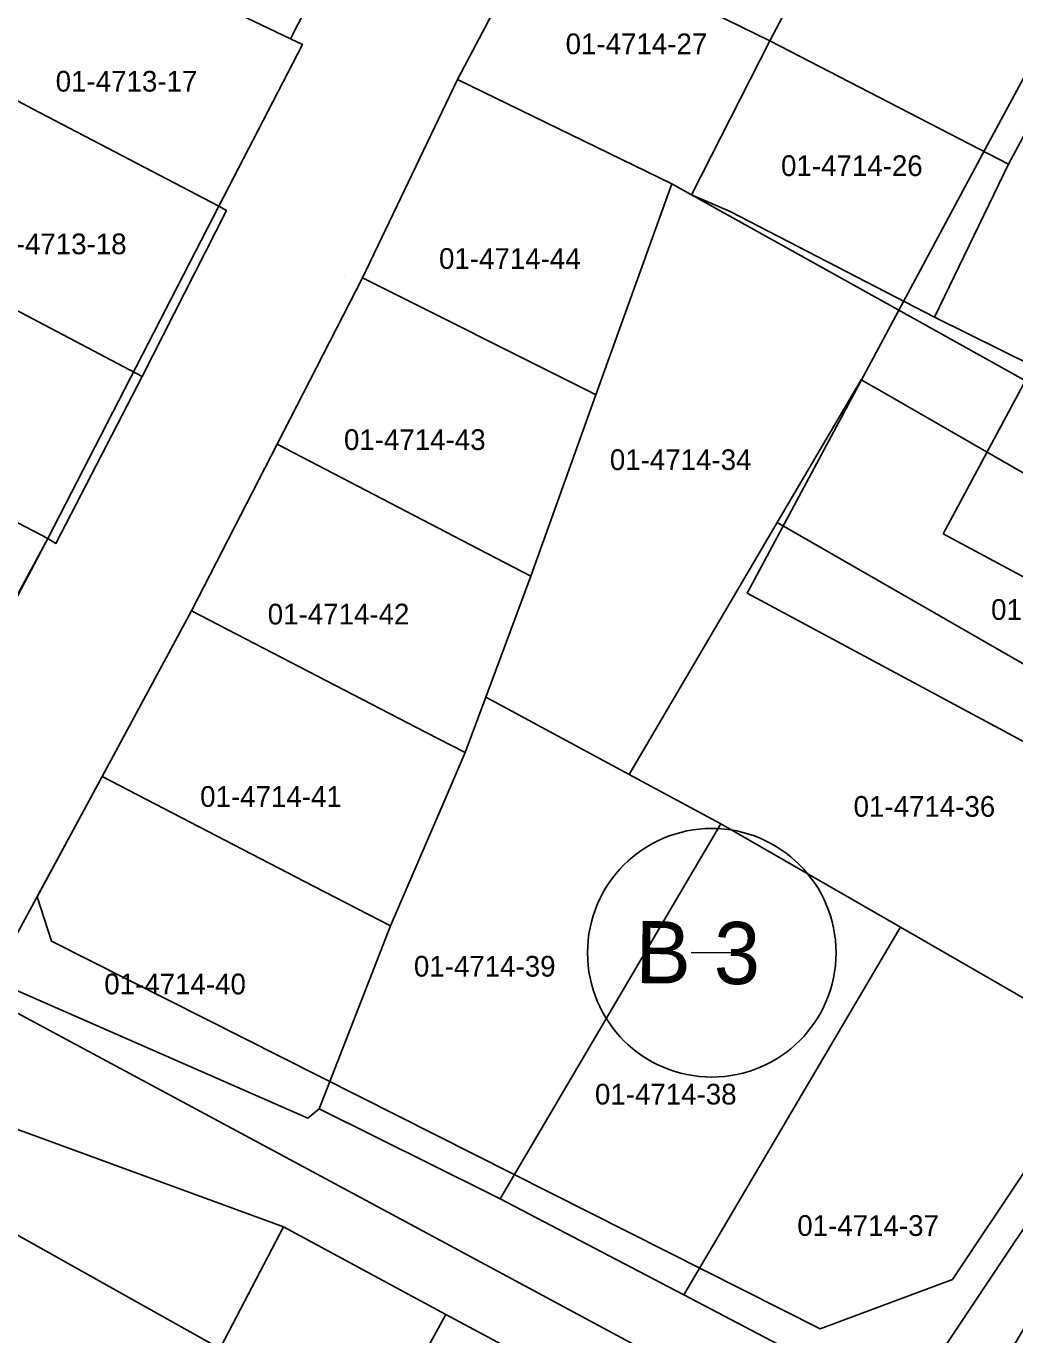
# Model space of a CAD drawing. Extents: x 413946 to 415528, y 4453939 to 4454944.
# Drawn here: x 415254.7 to 415302.5, y 4454047.3 to 4454110.5 of the extents above; entities that cross this region are included whole.
import ezdxf

# ---------------------------------------------------------------- set-up
doc = ezdxf.new("R2010")
doc.units = 0
for name, color, linetype in [('0_KADASTRO', 7, 'Continuous'), ('Level 27', 7, 'Continuous'), ('Level 28', 7, 'Continuous'), ('Level 29', 7, 'Continuous'), ('Level 32', 7, 'Continuous'), ('Level 62', 7, 'Continuous')]:
    doc.layers.add(name, color=color, linetype=linetype)

msp = doc.modelspace()

# ---------------------------------------------------------------- linework, layer by layer
at = {"layer": '0_KADASTRO'}
for points in [[(415256.281, 4454115.226), (415256.586, 4454115.802), (415256.59, 4454115.8), (415260.57, 4454123.3), (415271.63, 4454118.04), (415267.469, 4454109.879), (415258.256, 4454114.286), (415256.911, 4454114.927)], [(415279.41, 4454115.27), (415283.11, 4454122.3), (415294.37, 4454116.89), (415290.62, 4454109.78)], [(415290.62, 4454109.78), (415294.37, 4454116.89), (415305.98, 4454110.95), (415302.15, 4454103.83)], [(415252.633, 4454107.752), (415255.294, 4454113.204), (415256.281, 4454115.226), (415256.911, 4454114.927), (415258.256, 4454114.286), (415267.469, 4454109.879), (415268.046, 4454109.613), (415264.005, 4454101.803), (415255.011, 4454106.508)], [(415275.531, 4454107.926), (415279.41, 4454115.27), (415290.62, 4454109.78), (415286.84, 4454102.36), (415285.891, 4454102.887)], [(415286.84, 4454102.36), (415290.62, 4454109.78), (415302.15, 4454103.83), (415298.58, 4454096.45), (415288.7, 4454101.55)], [(415248.431, 4454099.833), (415252.633, 4454107.752), (415255.011, 4454106.508), (415264.005, 4454101.803), (415264.373, 4454101.599), (415260.299, 4454093.589), (415251.166, 4454098.394)], [(415270.941, 4454098.341), (415275.531, 4454107.926), (415285.891, 4454102.887), (415282.215, 4454092.703), (415281.807, 4454092.907)], [(415276.902, 4454078.113), (415279.074, 4454083.953), (415282.215, 4454092.703), (415285.891, 4454102.887), (415286.84, 4454102.36), (415297.69, 4454096.32), (415303.03, 4454093.35), (415313.42, 4454087.57), (415323.208, 4454082.121), (415321.05, 4454078.499), (415311.131, 4454084.191), (415301.426, 4454089.76), (415296.11, 4454092.81), (415295.029, 4454093.43), (415290.972, 4454086.535), (415283.887, 4454074.494), (415283.821, 4454074.383), (415277.14, 4454077.99)], [(415286.84, 4454102.36), (415288.7, 4454101.55), (415298.58, 4454096.45), (415303.35, 4454094.09), (415312.99, 4454088.83), (415313.9, 4454088.28), (415314.6, 4454087.8), (415315.34, 4454087.3), (415323.54, 4454082.68), (415323.208, 4454082.121), (415313.42, 4454087.57), (415303.03, 4454093.35), (415297.69, 4454096.32)], [(415244.266, 4454091.745), (415244.9, 4454092.977), (415248.431, 4454099.833), (415251.166, 4454098.394), (415260.299, 4454093.589), (415256.135, 4454085.53), (415255.747, 4454085.765), (415246.535, 4454090.563)], [(415266.827, 4454090.321), (415270.941, 4454098.341), (415281.807, 4454092.907), (415282.215, 4454092.703), (415279.074, 4454083.953), (415276.558, 4454085.261)], [(415290.972, 4454086.535), (415295.029, 4454093.43), (415296.11, 4454092.81), (415301.426, 4454089.76), (415311.131, 4454084.191), (415321.05, 4454078.499), (415320.24, 4454077.14), (415316.991, 4454071.605)], [(415240.333, 4454083.753), (415241.627, 4454086.382), (415244.266, 4454091.745), (415246.535, 4454090.563), (415255.747, 4454085.765), (415251.544, 4454077.816), (415243.486, 4454082.08)], [(415262.693, 4454082.272), (415266.827, 4454090.321), (415276.558, 4454085.261), (415279.074, 4454083.953), (415276.902, 4454078.113), (415275.905, 4454075.434), (415273.994, 4454076.423)], [(415283.821, 4454074.383), (415283.887, 4454074.494), (415290.972, 4454086.535), (415316.991, 4454071.605), (415309.889, 4454059.54), (415296.931, 4454067.017), (415293.937, 4454068.733), (415288.255, 4454071.99)], [(415258.369, 4454074.275), (415262.693, 4454082.272), (415273.994, 4454076.423), (415275.905, 4454075.434), (415275.131, 4454073.641), (415272.298, 4454067.079), (415268.586, 4454068.997)], [(415268.86, 4454058.25), (415271.25, 4454064.388), (415272.298, 4454067.079), (415275.131, 4454073.641), (415275.905, 4454075.434), (415276.902, 4454078.113), (415277.14, 4454077.99), (415283.821, 4454074.383), (415288.255, 4454071.99), (415277.6, 4454053.893), (415277.05, 4454054.18)], [(415253.067, 4454064.467), (415253.913, 4454066.049), (415258.369, 4454074.275), (415268.586, 4454068.997), (415272.298, 4454067.079), (415271.25, 4454064.388), (415268.86, 4454058.25), (415268.311, 4454057.798)], [(415277.6, 4454053.893), (415288.255, 4454071.99), (415293.937, 4454068.733), (415296.931, 4454067.017), (415296.85, 4454066.88), (415286.468, 4454049.271), (415286.069, 4454049.479)], [(415286.468, 4454049.271), (415296.85, 4454066.88), (415296.931, 4454067.017), (415309.889, 4454059.54), (415299.75, 4454042.3)], [(415217.722, 4453978.272), (415250.148, 4454058.75), (415267.134, 4454052.551), (415263.176, 4454044.967), (415262.422, 4454043.523), (415261.455, 4454041.584), (415258.808, 4454036.274), (415256.162, 4454028.807), (415253.432, 4454020.879), (415252.517, 4454012.444), (415252.323, 4454008.095), (415251.863, 4453997.942), (415251.451, 4453990.792), (415245.606, 4453981.485), (415247.775, 4453980.242), (415245.659, 4453974.735), (415240.717, 4453961.875)], [(415262.422, 4454043.523), (415263.176, 4454044.967), (415267.134, 4454052.551), (415274.967, 4454048.311), (415271.367, 4454041.734), (415270.899, 4454040.878), (415270.136, 4454039.484), (415266.588, 4454041.342)], [(415270.136, 4454039.484), (415270.899, 4454040.878), (415271.367, 4454041.734), (415274.967, 4454048.311), (415282.013, 4454044.558), (415277.472, 4454035.972), (415277.312, 4454035.67), (415271.061, 4454038.992)]]:
    msp.add_lwpolyline(points, close=True, dxfattribs=at)
at = {"layer": 'Level 27'}
for points in [[(415299.725, 4454171.468), (415296.47, 4454165.62), (415292.19, 4454157.74), (415287.94, 4454149.88), (415283.73, 4454141.97), (415279.73, 4454133.91), (415275.61, 4454125.95), (415271.63, 4454118.04), (415267.47, 4454109.88), (415268.046, 4454109.613), (415264.005, 4454101.803), (415255.747, 4454085.765), (415247.367, 4454070.245)], [(415255.235, 4454068.478), (415258.369, 4454074.275), (415262.693, 4454082.272), (415266.827, 4454090.321), (415270.941, 4454098.341), (415275.531, 4454107.926), (415279.41, 4454115.27), (415283.11, 4454122.3), (415287.21, 4454130.12), (415291.29, 4454138.02), (415295.54, 4454145.93), (415299.8, 4454153.95), (415303.98, 4454161.91), (415307.817, 4454169.556)], [(415270.066, 4454098.408), (415270.066, 4454098.408)], [(415310.173, 4454066.081), (415299.437, 4454050.012)]]:
    msp.add_lwpolyline(points, dxfattribs=at)
at = {"layer": 'Level 28'}
for p, q in [((415315.424, 4454077.161), (415298.995, 4454085.989)), ((415289.517, 4454083.136), (415311.578, 4454071.281))]:
    msp.add_line(p, q, dxfattribs=at)
at = {"layer": 'Level 29'}
for points in [[(415329.481, 4454158.218), (415325.768, 4454151.292), (415321.641, 4454143.557), (415317.51, 4454135.887), (415313.245, 4454127.769), (415309.081, 4454119.863), (415304.937, 4454111.814), (415301.136, 4454104.768), (415289.517, 4454083.136)], [(415298.995, 4454085.989), (415307.3, 4454101.45), (415311.13, 4454108.55), (415315.29, 4454116.63), (415319.44, 4454124.51), (415323.69, 4454132.6), (415327.81, 4454140.25), (415331.94, 4454147.99), (415335.775, 4454155.142)], [(415299.437, 4454050.012), (415293.052, 4454047.628), (415255.931, 4454066.338), (415255.235, 4454068.478)]]:
    msp.add_lwpolyline(points, dxfattribs=at)
at = {"layer": 'Level 32'}
msp.add_line((415288.815, 4454065.765), (415286.815, 4454065.785), dxfattribs=at)
msp.add_circle((415287.815, 4454065.775), 6, dxfattribs=at)
at = {"layer": 'Level 62'}
for p, q in [((415228.06, 4454066.792), (415259.518, 4454049.222)), ((415271.746, 4454053.478), (415264.858, 4454057.174)), ((415259.518, 4454049.222), (415267.895, 4454044.538))]:
    msp.add_line(p, q, dxfattribs=at)
for points in [[(415264.858, 4454057.174), (415233.074, 4454074.229)], [(415311.5, 4454065.366), (415297.178, 4454043.932)], [(415291.961, 4454042.63), (415271.746, 4454053.478)]]:
    msp.add_lwpolyline(points, dxfattribs=at)

# ---------------------------------------------------------------- texts
at = {"layer": '0_KADASTRO'}
for s, p in [('01-4714-27', (415280.757, 4454109.141)), ('01-4713-17', (415256.127, 4454107.336)), ('01-4714-26', (415291.161, 4454103.261)), ('01-4713-18', (415252.711, 4454099.487)), ('01-4714-44', (415274.642, 4454098.78)), ('01-4714-43', (415270.051, 4454090.04)), ('01-4714-34', (415282.892, 4454089.071)), ('01-4714-35', (415301.305, 4454081.841)), ('01-4714-42', (415266.369, 4454081.619)), ('01-4714-41', (415263.105, 4454072.816)), ('01-4714-36', (415294.665, 4454072.339)), ('01-4714-39', (415273.429, 4454064.624)), ('01-4714-40', (415258.474, 4454063.767)), ('01-4714-38', (415282.173, 4454058.452)), ('01-4714-37', (415291.945, 4454052.109))]:
    msp.add_text(s, height=1, dxfattribs=at).set_placement(p)
at = {"layer": 'Level 32'}
msp.add_text('B 3', height=3, rotation=359.4141, dxfattribs=at).set_placement((415284.116, 4454064.312))

doc.saveas('drawing.dxf')
